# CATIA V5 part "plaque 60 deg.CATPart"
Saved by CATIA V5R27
Part number: plaque 60 deg
Material "Aluminium": density 2710 kg/m3, Young's modulus 7e+10 Pa, Poisson ratio 0.346, thermal expansion 2.36e-05 1/K
Bounding box of the stored display mesh (mm): x 0 to 6, y 24.919 to 175.081, z 0 to 200
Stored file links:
  \\triton.meca.polymtl.ca\usagers\zaoue\profiles\Desktop\varm_ass\structure prismatique\plaque 60 deg.CATPart
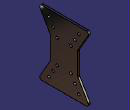
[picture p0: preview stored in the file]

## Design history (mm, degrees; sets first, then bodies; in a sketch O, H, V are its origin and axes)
Body1 (main body), material "Aluminium"
  Sketch1 on yz-plane, origin (0, 0, 0), H (0, 1, 0), V (0, 0, 1)
    line L1 (0, 0) -> (200, 0)
    line L2 (200, 0) -> (200, 200)
    line L3 (200, 200) -> (0, 200)
    line L4 (0, 200) -> (0, 0)
    length L2 = 200
    length L3 = 200
    horizontal: L1 H, L3 H
    vertical: L2 V, L4 V
  Pad1: profile Sketch1, direction (1, 0, 0), length 6
  Sketch2 on end face of Pad1, origin (6, 0, 0), H (0, 1, 0), V (0, 0, 1)
    construction line L1 (65.1208, 39.5875) -> (136.3144, 162.8984)
    construction line L2 (61.4715, 166.7334) -> (135.6839, 38.1937)
    reference projected line E1 (0, 200) -> (0, 0) from edge [face of Pad1 from Sketch1.L4 | end face of Pad1]
    point P5 (100, 100)
    reference projected line E2 (0, 0) -> (200, 0) from edge [face of Pad1 from Sketch1.L1 | end face of Pad1]
    reference projected line E3 (0, 200) -> (0, 0) from edge [face of Pad1 from Sketch1.L4 | end face of Pad1]
    circle A1 centre (146.188, 180) radius 4
    point P6 (146.188, 180)
    circle A2 centre (133.688, 158.3494) radius 4
    point P7 (133.688, 158.3494)
    circle A3 centre (121.188, 136.6987) radius 4
    point P8 (121.188, 136.6987)
    circle A4 centre (78.812, 63.3013) radius 4
    point P9 (78.812, 63.3013)
    circle A5 centre (66.312, 41.6506) radius 4
    point P10 (66.312, 41.6506)
    point P11 (64.312, 38.1865)
    circle A6 centre (53.812, 20) radius 4
    point P12 (53.812, 20)
    circle A7 centre (53.812, 180) radius 4
    point P13 (53.812, 180)
    point P14 (55.812, 176.5359)
    circle A8 centre (66.312, 158.3494) radius 4
    point P15 (66.312, 158.3494)
    circle A9 centre (78.812, 136.6987) radius 4
    point P16 (78.812, 136.6987)
    circle A10 centre (121.188, 63.3013) radius 4
    point P17 (121.188, 63.3013)
    circle A11 centre (133.688, 41.6506) radius 4
    point P18 (133.688, 41.6506)
    circle A12 centre (146.188, 20) radius 4
    point P19 (146.188, 20)
    reference projected line E4 (0, 0) -> (200, 0) from edge [face of Pad1 from Sketch1.L1 | end face of Pad1]
    reference projected line E5 (0, 0) -> (200, 0) from edge [face of Pad1 from Sketch1.L1 | end face of Pad1]
    reference projected line E6 (0, 0) -> (200, 0) from edge [face of Pad1 from Sketch1.L1 | end face of Pad1]
    reference projected line E7 (0, 0) -> (200, 0) from edge [face of Pad1 from Sketch1.L1 | end face of Pad1]
    angle L1 L2 = 120
    angle L2 E1 = 150
    distance P5 E2 = 100
    distance P5 E3 = 100
    radius A1 = 4
    radius A2 = 4
    radius A3 = 4
    radius A10 = 4
    radius A11 = 4
    radius A12 = 4
    radius A4 = 4
    radius A5 = 4
    radius A6 = 4
    radius A9 = 4
    radius A8 = 4
    radius A7 = 4
    distance P6 P7 = 25
    distance P7 P8 = 25
    distance P9 P10 = 25
    distance P12 P10 = 25
    distance P17 P18 = 25
    distance P18 P19 = 25
    distance P13 P15 = 25
    distance P15 P16 = 25
    distance P13 E4 = 180
    distance P12 E5 = 20
    distance P6 E6 = 180
    distance P19 E7 = 20
    coincidence: L1 P5, L2 P5, P6 L1, P7 L1, P8 L1, P9 L1, P10 L1, A5 P11, P11 L1, P12 L1, P13 L2, A7 P14, P14 L2, P15 L2, P16 L2, P17 L2, P18 L2, P19 L2
  Pocket1: profile Sketch2, direction (-1, 0, 0), through (limit type 3)
  Sketch3 on end face of Pad1, origin (6, 0, 0), H (0, 1, 0), V (0, 0, 1)
    line L1 (200, 200) -> (200, 0)
    point P1 (200, 200)
    reference projected line E1 (200, 0) -> (200, 200) from edge [face of Pad1 from Sketch1.L2 | end face of Pad1]
    construction line L2 (-15.862, 100) -> (174.2475, 100)
    reference projected line E2 (0, 0) -> (200, 0) from edge [face of Pad1 from Sketch1.L1 | end face of Pad1]
    reference projected point E3 (200, 200) from vertex [face of Pad1 from Sketch1.L3 | end face of Pad1 | face of Pad1 from Sketch1.L2]
    line L3 (200, 200) -> (179.7321, 200)
    line L4 (179.7321, 200) -> (142.2043, 135)
    line L5 (142.2043, 65) -> (179.7321, 0)
    line L6 (179.7321, 0) -> (200, 0)
    construction circle A1 centre (133.688, 158.3494) radius 6.4392
    point P7 (133.688, 158.3494)
    reference projected circle E4 centre (133.688, 158.3494) radius 4 from Sketch2.A2
    construction circle A2 centre (133.688, 41.6506) radius 8.5163
    point P8 (133.688, 41.6506)
    reference projected circle E5 centre (133.688, 41.6506) radius 4 from Sketch2.A11
    construction circle A3 centre (121.188, 63.3013) radius 5.314
    point P9 (121.188, 63.3013)
    construction circle A4 centre (121.188, 136.6987) radius 7.181
    point P10 (121.188, 136.6987)
    reference projected circle E6 centre (121.188, 136.6987) radius 4 from Sketch2.A3
    reference projected circle E7 centre (121.188, 63.3013) radius 4 from Sketch2.A10
    line L7 (142.2043, 135) -> (142.2043, 65)
    distance L2 E2 = 100
    length L1 = 200
    distance L4 P7 = 19.05
    distance L5 P8 = 19.05
    distance L4 P10 = 19.05
    length L7 = 70
    angle L7 L5 = 30
    vertical: L1 V, L7 V
    coincidence: L1 E1, P1 E3
    horizontal: L2 H, L3 H, L6 H
    concentricity: P7 E4, A2 E5, A4 E6, P9 E7
    tangency: L7 A2
  Pocket2: profile Sketch3, direction (-1, 0, 0), through (limit type 3)
  Mirror1: of Pocket2, about {plane type Offset, RefPlane zx-plane, Offset 100}
  Plane1: type Offset, RefPlane face of Pad1 from Sketch1.L1, Offset 99.9998
  Fillet1: radius 6.35, on edge [face of Pocket2 from Sketch3.L4 | face of Pad1 from Sketch1.L3]; edge [face of Pocket2 from Sketch3.L7 | face of Pocket2 from Sketch3.L4]; edge [face of Pocket2 from Sketch3.L5 | face of Pocket2 from Sketch3.L7]; edge [face of Pad1 from Sketch1.L1 | face of Pocket2 from Sketch3.L5]; edge [face of Mirror1 | face of Pad1 from Sketch1.L1]; edge [face of Mirror1 | face of Mirror1] (x2); edge [face of Pad1 from Sketch1.L3 | face of Mirror1]
  Plane2: type Offset, RefPlane face of Pocket2 from Sketch3.L7, Offset 42.2021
